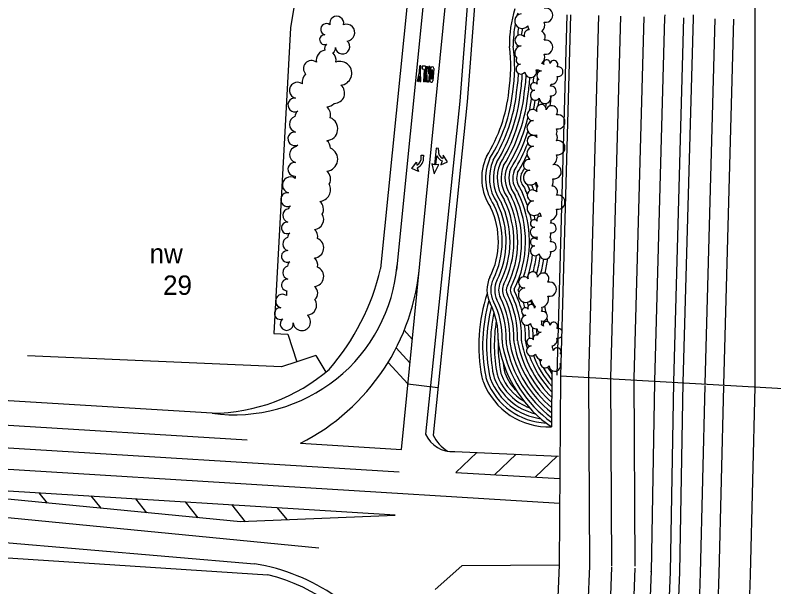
# Model space of a CAD drawing. Extents: x -9648 to 41057, y -12373 to 40276.
# Drawn here: x 8465.9 to 8856.8, y 12090.1 to 12384.5 of the extents above; entities that cross this region are included whole.
import ezdxf

# ---------------------------------------------------------------- set-up
doc = ezdxf.new("R2010")
doc.units = 0
for name, color, linetype in [('RD_P_GR_Rt', 7, 'Continuous'), ('SC_Scratch1', 7, 'Continuous'), ('SH_Data', 7, 'Continuous')]:
    doc.layers.add(name, color=color, linetype=linetype)

msp = doc.modelspace()

# ---------------------------------------------------------------- linework, layer by layer
at = {"layer": 'RD_P_GR_Rt'}
msp.add_line((8750.09, 12384.71), (8744.95, 12198.99), dxfattribs=at)
at = {"layer": 'SH_Data'}
for p, q in [((8846.95, 13279.24), (8846.95, 12193.08)), ((8721.3, 12923.78), (8654.16, 12253.91)), ((8729.59, 12922.95), (8662.45, 12253.08)), ((8724.57, 12723.12), (8694.96, 12340.13)), ((8728.42, 12722.82), (8698.81, 12339.83)), ((8618.49, 12445.79), (8607.82, 12377.92)), ((8674.34, 12256.44), (8691.59, 12430.07)), ((8752.09, 12384.65), (8746.95, 12198.8)), ((8766.4, 12384.26), (8761.24, 12197.98)), ((8777.82, 12383.94), (8772.67, 12197.67)), ((8789.85, 12383.61), (8784.7, 12197.33)), ((8800.54, 12383.31), (8795.36, 12196.03)), ((8800.58, 12384.65), (8800.54, 12383.31)), ((8810.3, 12383.04), (8805.11, 12195.48)), ((8815.16, 12382.91), (8809.97, 12195.2)), ((8815.21, 12384.65), (8815.16, 12382.91)), ((8826.45, 12382.6), (8821.25, 12194.55)), ((8836.08, 12382.33), (8830.87, 12194)), ((8607.82, 12377.92), (8599.27, 12220.52)), ((8673.29, 12350.4), (8674.21, 12355.34)), ((8674.21, 12355.34), (8674.42, 12358.34)), ((8674.91, 12358.3), (8674.42, 12358.34)), ((8674.71, 12355.31), (8674.91, 12358.3)), ((8674.95, 12350.28), (8674.71, 12355.31)), ((8675.66, 12358.25), (8675.55, 12356.59)), ((8676.71, 12356.51), (8675.55, 12356.59)), ((8677.33, 12358.14), (8675.66, 12358.25)), ((8676.71, 12356.51), (8676.28, 12350.19)), ((8677.33, 12358.14), (8676.78, 12350.16)), ((8677.82, 12358.11), (8677.28, 12350.12)), ((8677.82, 12358.11), (8678.32, 12358.07)), ((8678.32, 12358.07), (8678.73, 12354.28)), ((8678.99, 12358.03), (8678.73, 12354.28)), ((8679.49, 12357.99), (8678.94, 12350.01)), ((8679.49, 12357.99), (8678.99, 12358.03)), ((8679.93, 12357.13), (8679.5, 12350.81)), ((8680.35, 12355.93), (8680.08, 12351.94)), ((8681.01, 12355.88), (8680.74, 12351.89)), ((8681.59, 12357.01), (8681.16, 12350.7)), ((8673.79, 12350.36), (8674.3, 12353)), ((8674.45, 12350.32), (8674.3, 12353)), ((8678.03, 12353.83), (8677.78, 12350.09)), ((8678.45, 12350.04), (8678.03, 12353.83)), ((8673.29, 12350.4), (8673.79, 12350.36)), ((8674.45, 12350.32), (8674.95, 12350.28)), ((8676.78, 12350.16), (8676.28, 12350.19)), ((8677.78, 12350.09), (8677.28, 12350.12)), ((8678.94, 12350.01), (8678.45, 12350.04)), ((8694.96, 12340.23), (8677.4, 12168.59)), ((8698.81, 12339.83), (8681.25, 12168.2)), ((8682.83, 12316.02), (8681.9, 12307.4)), ((8684.07, 12315.88), (8682.83, 12316.02)), ((8683.96, 12314.89), (8684.07, 12315.88)), ((8675.06, 12312.33), (8676.3, 12312.42)), ((8675.14, 12311.33), (8675.06, 12312.33)), ((8676.3, 12312.42), (8676.38, 12311.43)), ((8682.73, 12307.31), (8683.23, 12312.02)), ((8686.36, 12312.28), (8686.19, 12310.62)), ((8688.68, 12308.93), (8686.36, 12312.28)), ((8670.24, 12305.51), (8672.66, 12308.79)), ((8672.66, 12308.79), (8672.79, 12307.13)), ((8685.88, 12309.38), (8685.17, 12307.46)), ((8685.17, 12307.46), (8688.68, 12308.93)), ((8673.71, 12303.94), (8670.24, 12305.51)), ((8673.05, 12305.88), (8673.71, 12303.94)), ((8681.9, 12307.4), (8680.52, 12307.88)), ((8680.52, 12307.88), (8681.81, 12302.72)), ((8681.81, 12302.72), (8684.17, 12307.49)), ((8684.17, 12307.49), (8682.73, 12307.31)), ((8664.96, 12160.8), (8674.34, 12256.44)), ((8666.39, 12222.18), (8670.54, 12217.68)), ((8599.27, 12220.52), (8606.34, 12220.13)), ((8606.34, 12220.13), (8611.09, 12205.89)), ((8662.25, 12213.11), (8669.34, 12205.43)), ((8603.22, 12203.27), (8472.34, 12208.97)), ((8620.8, 12209.13), (8611.09, 12205.89)), ((8620.8, 12209.13), (8625.91, 12200.55)), ((8611.09, 12205.89), (8603.22, 12203.27)), ((8658.05, 12205.63), (8668.27, 12194.55)), ((8742.48, 12201.47), (8742.24, 12172.39)), ((8746.95, 12198.8), (8746.17, 12101.27)), ((8746.95, 12198.8), (8861.73, 12192.24)), ((8567.4, 12179.43), (8275.53, 12197.41)), ((8761.24, 12197.98), (8761.82, 12100.62)), ((8772.66, 12198.05), (8773.24, 12100.69)), ((8784.69, 12198.12), (8785.27, 12100.76)), ((8795.35, 12195.46), (8793.57, 12097.84)), ((8795.36, 12196.03), (8795.35, 12195.46)), ((8805.1, 12195.29), (8803.33, 12097.66)), ((8809.97, 12195.2), (8808.19, 12097.57)), ((8668.27, 12194.55), (8683.75, 12192.64)), ((8821.23, 12193.71), (8818.89, 12096.87)), ((8830.85, 12193.47), (8828.51, 12096.64)), ((8846.95, 12193.08), (8844.61, 12096.25)), ((8274.76, 12184.85), (8585.5, 12165.7)), ((8274.04, 12173.22), (8663.83, 12149.2)), ((8612.91, 12164.01), (8664.96, 12160.8)), ((8273.38, 12162.36), (8746.42, 12133.21)), ((8688.66, 12159.91), (8745.8, 12157.29)), ((8688.66, 12159.91), (8745.8, 12157.29)), ((8693.02, 12148.96), (8703.81, 12159.22)), ((8712.96, 12147.77), (8724.03, 12158.29)), ((8733.82, 12146.52), (8745.18, 12157.32)), ((8693.02, 12148.96), (8746.52, 12145.76)), ((8582.11, 12123.49), (8341.67, 12146.9)), ((8341.67, 12146.9), (8661.67, 12127.18)), ((8622.36, 12109.91), (8340.74, 12137.32)), ((8478.16, 12138.49), (8482.39, 12133.2)), ((8505, 12136.83), (8510.06, 12130.5)), ((8527.86, 12135.42), (8533.63, 12128.21)), ((8553.51, 12133.84), (8560.07, 12125.64)), ((8577.36, 12132.37), (8584.39, 12123.58)), ((8600.82, 12130.93), (8605.99, 12124.47)), ((8661.63, 12126.75), (8582.11, 12123.49)), ((8337.07, 12123.49), (8589.3, 12101.95)), ((8332.15, 12113.46), (8596.11, 12096.27)), ((8746.17, 12101.27), (8696.06, 12100.81)), ((8746.17, 12101.27), (8744.3, 12056.63)), ((8696.06, 12100.81), (8682.28, 12088.74)), ((8761.82, 12100.62), (8738.73, 11548.41)), ((8773.22, 12100.14), (8750.13, 11547.93)), ((8785.23, 12099.64), (8762.13, 11547.43)), ((8793.58, 12098.1), (8778.08, 11670.69)), ((8803.33, 12097.75), (8787.82, 11670.34)), ((8808.19, 12097.57), (8792.69, 11670.16)), ((8793.57, 12097.84), (8793.58, 12098.1)), ((8818.9, 12097.18), (8803.4, 11669.77)), ((8828.52, 12096.83), (8813.02, 11669.42)), ((8844.61, 12096.25), (8829.11, 11668.84))]:
    msp.add_line(p, q, dxfattribs=at)
for points in [[(8727.44, 12296.75), (8728.28, 12295.51), (8728.93, 12294.16)], [(8729.12, 12297.84), (8730.02, 12296.51), (8730.73, 12295.02)], [(8731.99, 12297.04), (8732.54, 12295.88)], [(8733.83, 12297.81), (8734.34, 12296.75)], [(8722.48, 12293.38), (8723.06, 12292.52), (8723.52, 12291.57)], [(8724.13, 12294.51), (8724.8, 12293.51), (8725.32, 12292.43)], [(8725.79, 12295.63), (8726.54, 12294.51), (8727.12, 12293.3)], [(8715.85, 12288.9), (8716.1, 12288.53), (8716.3, 12288.12)], [(8717.51, 12290.02), (8717.84, 12289.52), (8718.1, 12288.98)], [(8719.16, 12291.14), (8719.58, 12290.52), (8719.91, 12289.85)], [(8720.82, 12292.26), (8721.32, 12291.52), (8721.71, 12290.71)], [(8712.54, 12286.66), (8712.62, 12286.53), (8712.69, 12286.4)], [(8714.2, 12287.78), (8714.36, 12287.53), (8714.49, 12287.26)]]:
    msp.add_lwpolyline(points, dxfattribs=at)
for centre, radius, start, end in [((8781.4, 12369.26), 60.85, 162.4048, 180.891), ((8739.2, 12384.44), 3.68, 259.1453, 101.4596), ((8631.6, 12380.24), 3.63, 349.1453, 191.4596), ((8727.08, 12381.4), 3.79, 96.1722, 320.5737), ((8781.4, 12369.26), 58.85, 163.9997, 165.3618), ((8626.3, 12377.14), 2.95, 53.83, 255.0376), ((8636.61, 12375.47), 4.33, 274.9476, 109.4572), ((8781.4, 12369.26), 58.85, 169.4523, 180.7739), ((8734.37, 12379.37), 4.39, 184.9476, 214.5187), ((8734.37, 12379.37), 4.39, 310.989, 19.4572), ((8781.4, 12369.26), 56.85, 171.0722, 175.3391), ((8781.4, 12369.26), 54.85, 171.2479, 174.7983), ((8730.67, 12374.36), 2.53, 87.8909, 205.9741), ((8736.06, 12373.32), 2.98, 323.83, 66.5449), ((8625.28, 12371.81), 2.5, 84.0047, 295.9741), ((8634.61, 12368.26), 3.74, 186.1722, 50.5737), ((8726.2, 12371.47), 2.82, 39.0625, 279.5412), ((8739.2, 12367.96), 3.68, 259.1453, 101.4596), ((8781.4, 12369.26), 42.85, 176.6234, 176.8897), ((8628.14, 12367.39), 2.79, 129.0625, 201.4567), ((8628.14, 12367.39), 2.79, 302.3756, 9.5412), ((8643.42, 12357.65), 77.87, 350.8189, 7.8756), ((8643.42, 12357.65), 79.87, 350.8598, 7.7867), ((8727.08, 12364.92), 3.79, 96.1722, 224.4883), ((8781.4, 12369.26), 56.85, 180.0817, 180.6523), ((8643.42, 12357.65), 81.87, 7.1444, 7.6997), ((8626.14, 12361.27), 5.14, 96.6825, 191.4596), ((8626.14, 12361.27), 5.14, 349.1453, 47.1497), ((8734.37, 12362.89), 4.39, 311.7888, 19.4572), ((8618.64, 12356.89), 4.17, 53.83, 222.9084), ((8633.22, 12354.53), 6.13, 274.9476, 109.4572), ((8726.56, 12356.71), 2.58, 96.1722, 320.5737), ((8725.96, 12361.18), 1.93, 145.8064, 279.5412), ((8643.42, 12357.65), 81.87, 0.9127, 1.2148), ((8736.76, 12357.77), 1.93, 39.0625, 73.8399), ((8739.8, 12359.74), 1.72, 354.0047, 205.9741), ((8743.48, 12359.03), 2.03, 323.83, 165.0376), ((8680.76, 12357.07), 0.833, 356.1075, 176.1075), ((8680.68, 12355.91), 0.333, 356.1075, 176.1075), ((8731.54, 12355.33), 2.99, 184.9476, 19.4572), ((8734.83, 12358.78), 2.51, 259.1453, 284.361), ((8737.36, 12353.3), 2.58, 96.1722, 230.1506), ((8643.42, 12357.65), 91.87, 358.2143, 359.1708), ((8736.76, 12357.77), 1.93, 227.1655, 279.5412), ((8745.62, 12355.37), 2.51, 259.1453, 101.4596), ((8618.92, 12350.14), 5.14, 130.4158, 191.4596), ((8680.41, 12351.92), 0.333, 176.1075, 356.1075), ((8643.42, 12357.65), 81.87, 350.8987, 357.7952), ((8643.42, 12357.65), 83.87, 350.9358, 357.6507), ((8643.42, 12357.65), 85.87, 350.9712, 357.2183), ((8643.42, 12357.65), 87.87, 351.0049, 356.5531), ((8643.42, 12357.65), 89.87, 354.8879, 356.916), ((8736.36, 12349.72), 1.72, 112.3611, 205.9741), ((8643.42, 12357.65), 91.87, 355.7414, 356.4859), ((8742.33, 12351.92), 2.99, 264.9285, 19.4572), ((8611.43, 12345.76), 4.17, 53.83, 255.0376), ((8630.39, 12344.34), 5.29, 269.2088, 50.5737), ((8680.33, 12350.75), 0.833, 176.1075, 356.1075), ((8733.31, 12347.75), 1.93, 39.0625, 279.5412), ((8740.04, 12349.02), 2.03, 323.83, 357.7946), ((8742.17, 12345.36), 2.51, 259.1453, 101.4596), ((8642.33, 12353.3), 78.38, 327.9304, 354.0866), ((8642.33, 12353.3), 80.38, 328.024, 354.046), ((8642.33, 12353.3), 82.38, 328.1178, 354.0073), ((8642.33, 12353.3), 84.38, 328.2124, 353.9704), ((8642.33, 12353.3), 86.38, 328.3082, 353.9353), ((8642.33, 12353.3), 88.38, 328.4058, 353.9017), ((8733.91, 12343.28), 2.58, 96.1722, 320.5737), ((8643.42, 12357.65), 89.87, 352.1786, 352.5492), ((8609.99, 12338.22), 3.53, 84.0047, 295.9741), ((8642.33, 12353.3), 90.38, 348.5558, 352.565), ((8642.33, 12353.3), 92.38, 349.0971, 352.1623), ((8642.33, 12353.3), 94.38, 350.6347, 352.7239), ((8738.88, 12341.9), 2.99, 184.9476, 19.4572), ((8642.33, 12353.3), 100.38, 351.0878, 353.7286), ((8643.42, 12357.65), 99.87, 351.179, 351.4803), ((8626.01, 12343.4), 6.13, 274.9476, 314.6658), ((8623.17, 12333.21), 5.29, 342.7472, 50.5737), ((8732.52, 12333.05), 2.82, 39.0625, 279.5412), ((8736.99, 12335.94), 2.53, 354.0047, 205.9741), ((8642.33, 12353.3), 96.38, 351.1087, 351.5709), ((8642.33, 12353.3), 98.38, 350.4021, 351.6514), ((8742.38, 12334.9), 2.98, 323.83, 165.0376), ((8611.43, 12328.29), 4.17, 108.8929, 255.0376), ((8614.02, 12331.98), 3.95, 129.0625, 176.4318), ((8626.01, 12325.93), 6.13, 274.9476, 68.7312), ((8642.33, 12353.3), 90.38, 328.5061, 346.1367), ((8745.52, 12329.54), 3.68, 259.1453, 101.4596), ((8733.4, 12326.5), 3.79, 96.1722, 286.4662), ((8642.33, 12353.3), 92.38, 345.3129, 345.5955), ((8609.99, 12320.75), 3.53, 84.0047, 295.9741), ((8642.33, 12353.3), 92.38, 328.61, 341.8872), ((8740.7, 12324.47), 4.39, 343.0947, 19.4572), ((8623.17, 12315.73), 5.29, 1.8566, 50.5737), ((8732.52, 12319.72), 2.82, 39.0625, 279.5412), ((8642.33, 12353.3), 94.38, 340.8567, 341.3303), ((8642.33, 12353.3), 96.38, 341.2595, 341.5009), ((8736.99, 12322.61), 2.53, 174.2986, 205.9741), ((8742.38, 12321.58), 2.98, 323.83, 32.8097), ((8745.52, 12316.21), 3.68, 259.1453, 101.4596), ((8611.43, 12312.65), 4.17, 98.9198, 255.0376), ((8614.02, 12314.51), 3.95, 129.0625, 145.0722), ((8626.01, 12310.29), 6.13, 274.9476, 66.3481), ((8642.33, 12353.3), 94.38, 328.7189, 338.3057), ((8733.4, 12313.17), 3.79, 96.1722, 233.477), ((8642.33, 12353.3), 96.38, 337.4589, 337.9028), ((8688.27, 12314.42), 5.58, 205.5275, 244.6518), ((8688.27, 12314.42), 4.33, 173.5731, 241.2011), ((8642.33, 12353.3), 96.38, 328.8348, 334.9794), ((8740.7, 12311.14), 4.39, 303.3879, 19.4572), ((8609.99, 12305.12), 3.53, 84.0047, 272.0587), ((8670.82, 12310.99), 4.33, 297.0911, 4.7192), ((8670.82, 12310.99), 5.58, 293.6405, 4.4713), ((8732.99, 12300.51), 26.7, 155.2481, 214.1018), ((8732.99, 12300.51), 24.7, 155.5372, 214.1018), ((8732.99, 12300.51), 22.7, 155.8596, 214.1018), ((8732.99, 12300.51), 20.7, 156.2233, 214.1018), ((8730.62, 12307.35), 2.82, 79.3276, 279.5412), ((8642.33, 12353.3), 98.38, 333.997, 334.1263), ((8623.17, 12300.1), 5.29, 330.2792, 50.5737), ((8732.99, 12300.51), 18.7, 156.639, 214.1018), ((8732.99, 12300.51), 16.7, 157.1217, 214.1018), ((8732.99, 12300.51), 14.7, 157.6936, 214.1018), ((8732.99, 12300.51), 12.7, 158.3882, 214.1018), ((8732.99, 12300.51), 10.7, 159.2603, 214.1018), ((8642.33, 12353.3), 98.38, 328.9612, 331.0129), ((8731.5, 12300.79), 3.79, 96.1722, 320.5737), ((8642.33, 12353.3), 100.38, 330.7346, 330.9599), ((8743.62, 12303.84), 3.68, 259.1453, 101.4596), ((8607.75, 12297.02), 4.17, 53.83, 255.0376), ((8615.25, 12301.4), 5.14, 177.9688, 191.4596), ((8732.99, 12300.51), 8.7, 160.4066, 214.1018), ((8732.99, 12300.51), 6.7, 162.0185, 214.1018), ((8738.79, 12298.76), 4.39, 328.4872, 19.4572), ((8622.33, 12294.66), 6.13, 274.9476, 27.3556), ((8673.97, 12267.89), 66.91, 24.6344, 25.5462), ((8738.79, 12298.76), 4.39, 184.9476, 214.3888), ((8736.99, 12294.53), 2.53, 135.8945, 205.9741), ((8742.38, 12293.49), 2.98, 323.83, 87.1919), ((8606.31, 12289.48), 3.53, 84.0047, 295.9741), ((8673.97, 12267.89), 56.91, 341.3252, 25.5462), ((8673.97, 12267.89), 58.91, 18.3936, 25.5462), ((8673.97, 12267.89), 60.91, 23.6271, 25.5462), ((8732.52, 12291.64), 2.82, 39.0625, 279.5412), ((8673.97, 12267.89), 62.91, 24.6325, 25.5462), ((8673.97, 12267.89), 64.91, 24.0764, 25.5462), ((8619.5, 12284.47), 5.29, 331.9902, 50.5737), ((8673.97, 12267.89), 48.91, 333.4408, 25.5462), ((8673.97, 12267.89), 50.91, 333.4408, 25.5462), ((8673.97, 12267.89), 52.91, 333.4408, 25.5462), ((8673.97, 12267.89), 54.91, 333.4408, 25.5462), ((8733.4, 12285.09), 3.79, 96.1722, 320.5737), ((8673.97, 12267.89), 60.91, 19.5624, 20.5282), ((8745.52, 12288.13), 3.68, 259.1453, 101.4596), ((8607.34, 12281.31), 3.53, 100.2969, 255.0376), ((8610.34, 12283.24), 3.95, 129.0625, 156.915), ((8673.97, 12267.89), 40.91, 333.4408, 25.5462), ((8673.97, 12267.89), 42.91, 333.4408, 25.5462), ((8673.97, 12267.89), 44.91, 333.4408, 25.5462), ((8673.97, 12267.89), 46.91, 333.4408, 25.5462), ((8619.71, 12279.31), 5.2, 274.9476, 30.9048), ((8673.97, 12267.89), 58.91, 10.3979, 13.8817), ((8673.97, 12267.89), 60.91, 10.5502, 12.7129), ((8736.36, 12279.17), 1.72, 70.0732, 205.9741), ((8673.97, 12267.89), 62.91, 11.7451, 12.7917), ((8740.7, 12283.06), 4.39, 184.9476, 211.1931), ((8740.7, 12283.06), 4.39, 287.6518, 19.4572), ((8606.12, 12274.92), 3, 84.0047, 295.9741), ((8733.31, 12277.2), 1.93, 39.0625, 279.5412), ((8740.04, 12278.46), 2.03, 323.83, 11.8697), ((8742.17, 12274.8), 2.51, 259.1453, 101.4596), ((8617.31, 12270.66), 4.49, 344.0534, 50.5737), ((8733.91, 12272.73), 2.58, 96.1722, 289.6917), ((8673.97, 12267.89), 58.91, 6.8073, 7.4264), ((8607.34, 12266.6), 3.53, 108.7398, 255.0376), ((8609.54, 12269.63), 3.35, 129.0625, 174.4969), ((8619.71, 12264.6), 5.2, 274.9476, 68.3847), ((8733.31, 12267.63), 1.93, 39.0625, 279.5412), ((8673.97, 12267.89), 58.91, 1.5674, 2.4203), ((8736.36, 12269.6), 1.72, 156.1839, 205.9741), ((8738.88, 12271.35), 2.99, 336.6145, 19.4572), ((8740.04, 12268.89), 2.03, 323.83, 38.4433), ((8733.91, 12263.16), 2.58, 96.1722, 320.5737), ((8673.97, 12267.89), 58.91, 357.6865, 357.9286), ((8742.17, 12265.24), 2.51, 259.1453, 101.4596), ((8606.12, 12260.21), 3, 84.0047, 295.9741), ((8738.88, 12261.78), 2.99, 184.9476, 19.4572), ((8609.54, 12254.91), 3.35, 129.0625, 174.4954), ((8617.31, 12255.95), 4.49, 344.0544, 50.5737), ((8673.97, 12267.89), 58.91, 341.4125, 353.2903), ((8673.97, 12267.89), 60.91, 345.1263, 353.1583), ((8673.97, 12267.89), 62.91, 344.6322, 352.8971), ((8673.97, 12267.89), 64.91, 345.3089, 351.9988), ((8673.97, 12267.89), 66.91, 345.8694, 352.4942), ((8578.78, 12262.9), 84.25, 262.2381, 355.248), ((8607.34, 12251.89), 3.53, 108.7397, 255.0376), ((8562.09, 12264.41), 112.53, 296.8469, 355.9362), ((8619.71, 12249.89), 5.2, 274.9476, 68.3844), ((8535.86, 12281.61), 121.51, 319.0839, 346.8207), ((8723.98, 12242.89), 15, 153.4408, 206.7882), ((8728.12, 12246.85), 2.82, 39.0625, 279.5412), ((8732.58, 12249.74), 2.53, 354.0047, 205.9741), ((8737.98, 12248.71), 2.98, 323.83, 165.0376), ((8606.12, 12245.49), 3, 84.0047, 267.214), ((8723.98, 12242.89), 13, 153.4408, 206.7882), ((8723.98, 12242.89), 11, 153.4408, 206.7882), ((8723.98, 12242.89), 9, 153.4408, 206.7882), ((8723.98, 12242.89), 7, 153.4408, 206.7882), ((8741.12, 12243.34), 3.68, 259.1453, 101.4596), ((8610.02, 12240.89), 4.36, 158.3633, 191.4596), ((8617.31, 12241.24), 4.49, 313.5988, 50.5737), ((8723.98, 12242.89), 5, 153.4408, 206.7882), ((8723.98, 12242.89), 3, 153.4408, 206.7882), ((8723.98, 12242.89), 1, 153.4408, 206.7882), ((8675.25, 12218.29), 53.59, 15.3049, 26.7882), ((8673.97, 12267.89), 56.91, 333.9454, 336.2074), ((8675.25, 12218.29), 55.59, 25.1615, 26.2714), ((8728.99, 12240.3), 3.79, 96.1722, 320.5737), ((8673.97, 12267.89), 58.91, 335.9561, 336.1202), ((8603.67, 12237.18), 3.53, 53.83, 255.0376), ((8616.03, 12235.17), 5.2, 274.9476, 32.7664), ((8788.66, 12214.55), 83.89, 161.5458, 191.388), ((8675.25, 12218.29), 43.59, 358.3063, 26.7882), ((8675.25, 12218.29), 45.59, 358.3063, 26.7882), ((8675.25, 12218.29), 47.59, 358.3063, 26.7882), ((8675.25, 12218.29), 49.59, 358.3063, 26.7882), ((8675.25, 12218.29), 51.59, 358.3063, 26.7882), ((8736.29, 12238.27), 4.39, 184.9476, 239.0896), ((8736.29, 12238.27), 4.39, 283.4263, 19.4572), ((8602.44, 12230.78), 3, 84.0047, 295.9741), ((8788.66, 12214.55), 81.89, 163.8024, 191.388), ((8788.66, 12214.55), 79.89, 165.4738, 191.388), ((8675.25, 12218.29), 39.59, 358.3063, 26.7882), ((8675.25, 12218.29), 41.59, 358.3063, 26.7882), ((8728.77, 12231.83), 1.93, 39.0625, 279.5412), ((8675.25, 12218.29), 55.59, 16.1454, 19.3849), ((8675.25, 12218.29), 57.59, 16.6718, 18.5477), ((8731.81, 12233.79), 1.72, 354.0047, 205.9741), ((8675.25, 12218.29), 59.59, 16.7291, 18.8894), ((8735.49, 12233.09), 2.03, 135.7292, 165.0376), ((8735.49, 12233.09), 2.03, 323.83, 26.7868), ((8675.25, 12218.29), 65.59, 11.158, 14.4472), ((8613.63, 12226.53), 4.49, 186.1722, 50.5737), ((8788.66, 12214.55), 77.89, 167.5242, 191.388), ((8729.37, 12227.36), 2.58, 96.1722, 320.5737), ((8675.25, 12218.29), 53.59, 11.8864, 13.0839), ((8737.63, 12229.43), 2.51, 259.1453, 101.4596), ((8605.86, 12225.49), 3.35, 129.0625, 9.5412), ((8788.66, 12214.55), 75.89, 170.4286, 191.388), ((8734.34, 12225.97), 2.99, 339.383, 19.4572), ((8739.7, 12225.03), 1.72, 354.0047, 205.9741), ((8675.25, 12218.29), 63.59, 7.0605, 7.8733), ((8675.25, 12218.29), 65.59, 7.3135, 9.0969), ((8743.38, 12224.32), 2.03, 323.83, 165.0376), ((8675.25, 12218.29), 53.59, 358.3063, 7.1387), ((8675.25, 12218.29), 55.59, 359.5817, 6.9379), ((8734.34, 12225.97), 2.99, 184.9476, 277.5364), ((8675.25, 12218.29), 57.59, 359.039, 5.2316), ((8675.25, 12218.29), 59.59, 1.347, 4.5339), ((8736.66, 12223.06), 1.93, 181.3959, 279.5412), ((8736.66, 12223.06), 1.93, 39.0625, 75.5235), ((8745.52, 12220.66), 2.51, 34.2584, 101.4596), ((8734.44, 12218.01), 1.72, 74.3656, 205.9741), ((8737.25, 12218.59), 2.58, 96.1722, 155.2523), ((8742.23, 12217.2), 2.99, 278.948, 19.4572), ((8745.52, 12220.66), 2.51, 259.1453, 322.5713), ((8788.66, 12214.55), 73.89, 177.7607, 191.388), ((8729.82, 12216.68), 15, 178.3063, 191.0585), ((8729.82, 12216.68), 13, 178.3063, 191.0585), ((8729.82, 12216.68), 11, 178.3063, 191.0585), ((8779.44, 12226.37), 61.56, 191.0585, 232.873), ((8729.82, 12216.68), 9, 178.3063, 191.0585), ((8779.44, 12226.37), 59.56, 191.0585, 231.4268), ((8729.82, 12216.68), 7, 178.3063, 191.0585), ((8779.44, 12226.37), 57.56, 191.0585, 229.8478), ((8729.82, 12216.68), 5, 178.3063, 191.0585), ((8779.44, 12226.37), 55.56, 191.0585, 228.1138), ((8729.82, 12216.68), 3, 178.3063, 191.0585), ((8779.44, 12226.37), 53.56, 191.0585, 226.1971), ((8729.82, 12216.68), 1, 178.3063, 191.0585), ((8779.44, 12226.37), 51.56, 191.0585, 195.2969), ((8731.4, 12216.04), 1.93, 39.0625, 279.5412), ((8740.26, 12213.65), 2.51, 346.5612, 13.9284), ((8779.44, 12226.37), 65.56, 191.0585, 235.4339), ((8779.44, 12226.37), 63.56, 191.0585, 234.2039), ((8731.99, 12211.57), 2.58, 96.1722, 320.5737), ((8779.44, 12226.37), 49.56, 194.3213, 194.3478), ((8741.46, 12211.87), 1.72, 354.0047, 43.8122), ((8745.13, 12211.17), 2.03, 323.83, 165.0376), ((8779.44, 12226.37), 51.56, 199.3577, 224.0614), ((8779.44, 12226.37), 49.56, 200.3069, 221.6583), ((8736.97, 12210.19), 2.99, 184.9476, 272.9421), ((8779.44, 12226.37), 47.56, 203.4722, 205.4081), ((8739.01, 12205.43), 2.58, 136.809, 320.5737), ((8747.27, 12207.51), 2.51, 90.3384, 101.4596), ((8788.66, 12214.55), 71.89, 187.4545, 191.388), ((8779.44, 12226.37), 47.56, 209.354, 218.9199), ((8779.44, 12226.37), 45.56, 210.6324, 215.7469), ((8743.98, 12204.05), 2.99, 184.9476, 19.4572), ((8747.27, 12207.51), 2.51, 259.1453, 266.4913), ((8566.79, 12272.72), 93.29, 270.3766, 310.7411), ((8721.13, 12200.95), 11, 191.388, 201.1691), ((8721.13, 12200.95), 9, 191.388, 201.1691), ((8721.13, 12200.95), 7, 191.388, 201.1691), ((8721.13, 12200.95), 5, 191.388, 201.1691), ((8740.96, 12208.63), 26.26, 201.1691, 240.2186), ((8721.13, 12200.95), 3, 191.388, 201.1691), ((8740.96, 12208.63), 24.26, 201.1691, 226.1976), ((8721.13, 12200.95), 15, 191.388, 201.1691), ((8740.96, 12208.63), 36.26, 201.1691, 272.0253), ((8721.13, 12200.95), 13, 191.388, 201.1691), ((8740.96, 12208.63), 34.26, 201.1691, 267.5276), ((8740.96, 12208.63), 32.26, 201.1691, 262.4412), ((8740.96, 12208.63), 30.26, 201.1691, 256.5373), ((8740.96, 12208.63), 28.26, 201.1691, 249.4136), ((8691.16, 12174.8), 15.1, 204.2664, 274.2772), ((8699.5, 12177.06), 20.29, 205.9014, 237.72), ((8572.53, 12000.3), 103.02, 29.9882, 80.6301), ((8574.35, 12006.59), 92.28, 29.1236, 76.3596)]:
    msp.add_arc(centre, radius, start, end, dxfattribs=at)

# ---------------------------------------------------------------- texts
at = {"layer": 'SC_Scratch1'}
for s, p in [('nw', (8535.21, 12256.7)), ('29', (8542.15, 12240.41))]:
    msp.add_text(s, height=10, dxfattribs=at).set_placement(p)

doc.saveas('drawing.dxf')
